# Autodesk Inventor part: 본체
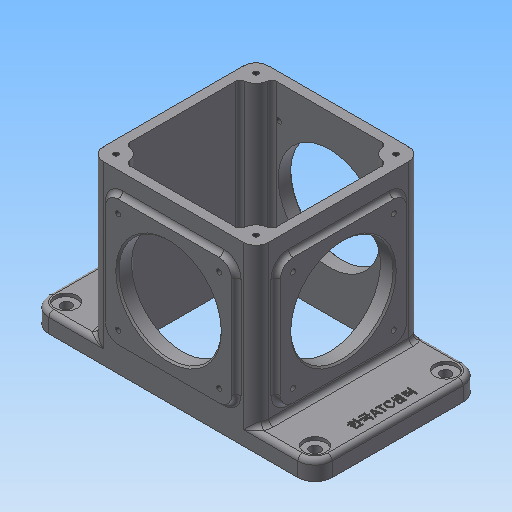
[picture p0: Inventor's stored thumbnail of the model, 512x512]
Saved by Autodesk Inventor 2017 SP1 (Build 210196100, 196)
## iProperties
Created: 2018-09
Part Number: 본체
Material: 일반
Document SubType Name: Modeling
Designer: mduedu
Density: 1 g/cm^3
Mass: 359.032 g
Surface Area: 957.184 cm^2
Volume: 359.032 cm^3
Appearance: 기본값
Author: mduedu
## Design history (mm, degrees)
sketch "스케치1"
  geometry: L1 (90, 52.5)-(-90, 52.5); L2 (-90, 52.5)-(-90, -52.5); L3 (-90, -52.5)-(90, -52.5); L4 (90, -52.5)-(90, 52.5); L5 (90, 52.5)-(-90, -52.5); L6 (-90, 52.5)-(90, -52.5); 1 further point
  constraints: 12 end point, 2 midpoint, 2 parallel, 1 horizontal, 1 perpendicular
  dimensions: "d0" = 180 distance of L3.end L2.end; "d1" = 105 distance of L2.end L1.end
extrude "돌출1" new body sketch "스케치1" distance "d2" = 12; taper "d3" = 0 deg
sketch "스케치2"
  geometry: L1 (-52.5, -52.5)-(52.5, -52.5); L2 (52.5, -52.5)-(52.5, 52.5); L3 (52.5, 52.5)-(-52.5, 52.5); L4 (-52.5, 52.5)-(-52.5, -52.5); L5 (-52.5, -52.5)-(52.5, 52.5); L6 (52.5, -52.5)-(-52.5, 52.5); 1 further point
  constraints: 12 end point, 2 midpoint, 2 parallel, 1 horizontal, 1 perpendicular
  dimensions: "d4" = 105 distance of L3.end L2.end; "d5" = 105 distance of L2.end L1.end
extrude "돌출2" join sketch "스케치2" distance "d6" = 100; taper "d7" = 0 deg
sketch "스케치14"
  geometry: L1 (-52.5, 52.5)-(52.5, 52.5) reference; L2 (52.5, 52.5)-(52.5, -52.5) reference; L3 (52.5, -52.5)-(-52.5, -52.5) reference; L4 (-52.5, -52.5)-(-52.5, 52.5) reference; L5 (46.5, 46.5)-(-46.5, 46.5); L6 (-46.5, 46.5)-(-46.5, -46.5); L7 (-46.5, -46.5)-(46.5, -46.5); L8 (46.5, -46.5)-(46.5, 46.5); 1 further point
  constraints: 8 end point, 3 other
  dimensions: "d85" = 6 distance between parallel lines of L5 L1
extrude "돌출10" cut sketch "스케치14" stored distance "d86" = 10; taper "d87" = 0 deg
fillet "모깎기1" dims "d12" = 8
sketch "스케치15"
  geometry: A1 r 8 centre (-44.5, 44.5) between (-44.5, 52.5) and (-52.5, 44.5) reference; A2 r 8 centre (44.5, 44.5) between (52.5, 44.5) and (44.5, 52.5) reference; A3 r 8 centre (44.5, -44.5) between (44.5, -52.5) and (52.5, -44.5) reference; A4 r 8 centre (-44.5, -44.5) between (-52.5, -44.5) and (-44.5, -52.5) reference; 5 further points
  constraints: 4 coincident, 4 vertical alignment, 8 other
extrude "돌출11" join sketch "스케치15" stored distance "d88" = 10; taper "d89" = 0 deg
fillet "모깎기15" dims "d90" = 3
sketch "스케치6"
  geometry: L1 (50, 19)-(130, 19); L2 (130, 19)-(130, 99); L3 (130, 99)-(50, 99); L4 (50, 99)-(50, 19); L5 (50, 19)-(130, 99); L6 (130, 19)-(50, 99); L7 (0, 0)-(180, 0) reference; 4 further points
  constraints: 12 end point, 4 midpoint, 2 parallel, 1 horizontal, 1 perpendicular, 1 vertical alignment
  dimensions: "d25" = 80 distance of L3.end L2.end; "d26" = 80 distance of L2.end L1.end; "d27" = 59 distance of point (90, 0) point (90, 59)
extrude "돌출6" join sketch "스케치6" distance "d28" = 3; taper "d29" = 0 deg
fillet "모깎기7" dims "d30" = 8
sketch "스케치7"
  geometry: C1 r 32.5 at (90, 59); 1 further point
  constraints: 1 centre point, 1 vertical alignment
  dimensions: "d32" = 65 diameter of C1; "d33" = 59 distance of C1.centre point (90, 0)
extrude "돌출7" cut sketch "스케치7" stored distance "d34" = 3; taper "d35" = 0 deg
fillet "모깎기9" dims "d36" = 3
sketch "스케치8"
  geometry: L1 (4.5, 7)-(84.5, 7); L2 (84.5, 7)-(84.5, 87); L3 (84.5, 87)-(4.5, 87); L4 (4.5, 87)-(4.5, 7); L5 (4.5, 7)-(84.5, 87); L6 (84.5, 7)-(4.5, 87); L7 (-8, -12)-(97, -12) reference; C1 r 32.5 at (44.5, 47); 4 further points
  constraints: 12 end point, 4 midpoint, 2 parallel, 1 centre point, 1 coincident, 1 horizontal, 1 perpendicular, 1 vertical alignment
  dimensions: "d37" = 80 distance of L3.end L2.end; "d38" = 80 distance of L2.end L1.end; "d39" = 59 distance from line of point (44.5, 47) L7; "d40" = 65 diameter of C1
extrude "돌출8" join sketch "스케치8" distance "d41" = 3; taper "d42" = 0 deg
fillet "모깎기10" dims "d43" = 8
extrude "돌출9" cut sketch "스케치8" stored distance "d44" = 3; taper "d45" = 0 deg
fillet "모깎기11" dims "d46" = 3
sketch "스케치9"
  geometry: L1 (50, 91)-(50, 27) reference; L2 (58, 19)-(122, 19) reference; L3 (130, 27)-(130, 91) reference; L4 (122, 99)-(58, 99) reference; C1 r 32.5 at (90, 59) reference; A1 r 8 centre (58, 91) between (58, 99) and (50, 91) reference; A2 r 8 centre (58, 27) between (50, 27) and (58, 19) reference; A3 r 8 centre (122, 27) between (122, 19) and (130, 27) reference; A4 r 8 centre (122, 91) between (130, 91) and (122, 99) reference; 5 further points
  constraints: 4 coincident
hole "구멍1" sketch "스케치9" at (58, 91), (122, 91), (122, 27), (58, 27) diameter "d47" = 3.242; stored, may be unused: countersink angle "d51" = 90 deg, drill point angle "d53" = 118 deg; dims "d48" = 6, "d49" = 4, "d50" = 2, "d52" = 9
sketch "스케치10"
  geometry: L1 (12.5, 7)-(76.5, 7) reference; L2 (84.5, 15)-(84.5, 79) reference; L3 (76.5, 87)-(12.5, 87) reference; L4 (4.5, 79)-(4.5, 15) reference; C1 r 32.5 at (44.5, 47) reference; A1 r 8 centre (12.5, 15) between (4.5, 15) and (12.5, 7) reference; A2 r 8 centre (76.5, 15) between (76.5, 7) and (84.5, 15) reference; A3 r 8 centre (76.5, 79) between (84.5, 79) and (76.5, 87) reference; A4 r 8 centre (12.5, 79) between (12.5, 87) and (4.5, 79) reference; 5 further points
  constraints: 4 coincident
hole "구멍2" sketch "스케치10" at (12.5, 79), (76.5, 79), (76.5, 15), (12.5, 15) diameter "d54" = 3.242; stored, may be unused: countersink angle "d58" = 90 deg, drill point angle "d60" = 118 deg; dims "d55" = 6, "d56" = 4, "d57" = 2, "d59" = 9
fillet "모깎기12" dims "d68" = 11
sketch "스케치16"
  geometry: A1 r 11 centre (-79, 41.5) between (-79, 52.5) and (-90, 41.5) reference; A2 r 11 centre (-79, -41.5) between (-90, -41.5) and (-79, -52.5) reference; A3 r 11 centre (79, 41.5) between (90, 41.5) and (79, 52.5) reference; A4 r 11 centre (79, -41.5) between (79, -52.5) and (90, -41.5) reference; 5 further points
  constraints: 4 coincident
hole "구멍5" sketch "스케치16" at (-79, 41.5), (79, 41.5), (79, -41.5), (-79, -41.5) diameter "d91" = 6.6; stored, may be unused: countersink angle "d95" = 90 deg, drill point angle "d97" = 118 deg; dims "d92" = 6, "d93" = 14, "d94" = 2, "d96" = 8
fillet "모깎기13" dims "d77" = 3
fillet "모깎기14" dims "d78" = 3
chamfer "모따기1" distance "d79" = 1; stored, may be unused: second distance "d80" = 2, angle "d81" = 45 deg
sketch "스케치17"
  geometry: A1 r 8 centre (-44.5, 44.5) between (-44.5, 52.5) and (-52.5, 44.5) reference; A2 r 8 centre (-44.5, -44.5) between (-52.5, -44.5) and (-44.5, -52.5) reference; A3 r 8 centre (44.5, -44.5) between (44.5, -52.5) and (52.5, -44.5) reference; A4 r 8 centre (44.5, 44.5) between (52.5, 44.5) and (44.5, 52.5) reference; 5 further points
  constraints: 4 coincident
hole "구멍6" sketch "스케치17" at (-44.5, 44.5), (44.5, 44.5), (44.5, -44.5), (-44.5, -44.5) diameter "d98" = 3.242; stored, may be unused: countersink angle "d102" = 90 deg, drill point angle "d104" = 118 deg; dims "d99" = 8, "d100" = 15, "d101" = 2, "d103" = 10
sketch "스케치13"
  geometry: L1 (90, -41.5)-(90, 41.5) reference; 2 further points
  constraints: 1 horizontal alignment, 1 other
  dimensions: "d82" = 10 distance from line of point (80, 0) L1
feature "엠보싱1" sketch "스케치13" dims "d0" = 180, "d1" = 105, "d25" = 80, "d26" = 80, "d27" = 59, "d83" = 0.5, "d84" = 0
node "솔리드1"
mirror "대칭1"
mirror "대칭2"
node "투영된 루프2"
node "투영된 루프3"
node "투영된 루프6"
